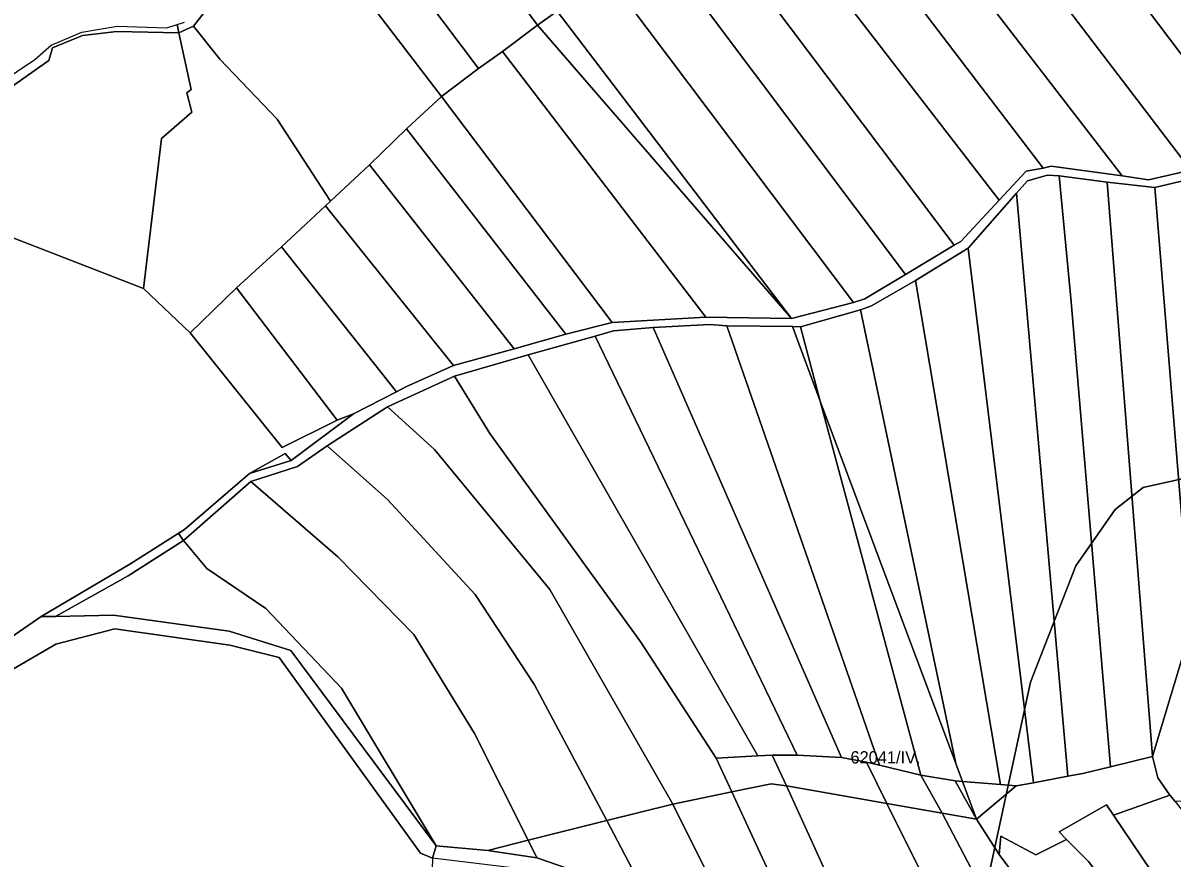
# Model space of a CAD drawing. Extents: x -521261 to -517465, y -1182764 to -1179456.
# Drawn here: x -520232.1 to -519763.3, y -1180556.2 to -1180215.6 of the extents above; entities that cross this region are included whole.
import ezdxf

# ---------------------------------------------------------------- set-up
doc = ezdxf.new("R2010")
doc.units = 0
for name, color, linetype in [('95560013', 7, 'Continuous'), ('95610013', 7, 'Continuous'), ('95620013', 7, 'Continuous'), ('95630013', 7, 'Continuous'), ('95640013', 7, 'Continuous'), ('95660013', 7, 'Continuous')]:
    doc.layers.add(name, color=color, linetype=linetype)

msp = doc.modelspace()

# ---------------------------------------------------------------- linework, layer by layer
at = {"layer": '95560013'}
for points in [[(-520022.17, -1180216.48), (-519918.48, -1180336.15), (-519953.52, -1180335.52), (-520036.42, -1180227.21)], [(-520036.42, -1180227.21), (-519953.52, -1180335.52), (-519991.66, -1180337.82), (-520061.32, -1180245.63), (-520046.22, -1180234.23)], [(-520061.32, -1180245.63), (-519991.66, -1180337.82), (-520010.61, -1180342.51), (-520075.57, -1180258.83)], [(-520075.57, -1180258.83), (-520010.61, -1180342.51), (-520031.68, -1180348.45), (-520090.76, -1180273.4)], [(-520090.76, -1180273.4), (-520031.68, -1180348.45), (-520056.48, -1180355.33), (-520108.66, -1180290.13), (-520106.59, -1180288.3)], [(-520108.66, -1180290.13), (-520056.48, -1180355.33), (-520075.93, -1180364.03), (-520079.72, -1180366), (-520126.56, -1180306.85)], [(-520126.56, -1180306.85), (-520079.72, -1180366), (-520097.16, -1180375.07), (-520103.92, -1180377.53), (-520144.91, -1180323.68)], [(-520163.84, -1180341.94), (-520144.91, -1180323.68), (-520103.92, -1180377.53), (-520126.31, -1180388.7)], [(-519991.21, -1180341.16), (-519975, -1180339.84), (-519898.1, -1180515.17), (-519916.26, -1180514.28), (-519998.64, -1180343.32)], [(-519951.87, -1180338.63), (-519944.96, -1180339.1), (-519882.63, -1180518.25), (-519887.93, -1180517.13), (-519898.1, -1180515.17), (-519975, -1180339.84)], [(-519918.17, -1180339.42), (-519906.77, -1180369.91), (-519865.71, -1180522.36), (-519882.63, -1180518.25), (-519944.96, -1180339.1)], [(-519998.64, -1180343.32), (-519916.26, -1180514.28), (-519926.4, -1180514.22), (-519932.3, -1180514.44), (-520025.91, -1180350.97)], [(-520056.04, -1180359.66), (-520025.91, -1180350.97), (-519932.3, -1180514.44), (-519949.33, -1180515.46), (-519979.96, -1180468.18), (-520041.61, -1180383.08)], [(-520056.04, -1180359.66), (-520041.61, -1180383.08), (-519979.96, -1180468.18), (-519949.33, -1180515.46), (-519942.92, -1180529.19), (-519966.95, -1180534.21), (-520017.18, -1180446.68), (-520064.12, -1180389.52), (-520083.39, -1180372.18)], [(-519906.77, -1180369.91), (-519851.55, -1180517.62), (-519848.8, -1180524.97), (-519851.74, -1180524.68), (-519865.71, -1180522.36)], [(-520083.39, -1180372.18), (-520064.12, -1180389.52), (-520017.18, -1180446.68), (-519966.95, -1180534.21), (-519993.87, -1180540.91), (-520023.31, -1180485.47), (-520047.54, -1180448.63), (-520083.31, -1180409.99), (-520107.95, -1180388.03)], [(-520120.07, -1180396.51), (-520107.95, -1180388.03), (-520083.31, -1180409.99), (-520047.54, -1180448.63), (-520023.31, -1180485.47), (-519993.87, -1180540.91), (-520025.98, -1180548.95), (-520047.89, -1180505.42), (-520072.54, -1180464.95), (-520103.68, -1180433.34), (-520139.1, -1180402.64)], [(-520139.1, -1180402.64), (-520103.68, -1180433.34), (-520072.54, -1180464.95), (-520047.89, -1180505.42), (-520025.98, -1180548.95), (-520042.35, -1180553.05), (-520063.47, -1180551.19), (-520102.14, -1180486.95), (-520132.98, -1180454.38), (-520157.02, -1180438.05), (-520166.58, -1180426.67)], [(-519926.4, -1180514.22), (-519920.55, -1180526.74), (-519926.76, -1180525.85), (-519942.92, -1180529.19), (-519949.33, -1180515.46), (-519932.3, -1180514.44)], [(-519916.26, -1180514.28), (-519898.1, -1180515.17), (-519887.93, -1180517.13), (-519879.66, -1180533.88), (-519920.55, -1180526.74), (-519926.4, -1180514.22)], [(-519882.63, -1180518.25), (-519865.71, -1180522.36), (-519857.1, -1180537.86), (-519879.66, -1180533.88), (-519887.93, -1180517.13)], [(-519926.76, -1180525.85), (-519920.55, -1180526.74), (-519881.21, -1180613), (-519902.42, -1180605.56), (-519908.84, -1180602.74), (-519942.92, -1180529.19)], [(-519865.71, -1180522.36), (-519851.74, -1180524.68), (-519843.08, -1180540.27), (-519857.1, -1180537.86)], [(-519851.74, -1180524.68), (-519848.8, -1180524.97), (-519843.08, -1180540.27)], [(-519942.92, -1180529.19), (-519908.84, -1180602.74), (-519920.76, -1180597.55), (-519921.12, -1180601.42), (-519937.24, -1180593.79), (-519966.95, -1180534.21)], [(-519879.66, -1180533.88), (-519853.6, -1180586.17), (-519837.56, -1180621.72), (-519856.32, -1180622.11), (-519868.13, -1180619.64), (-519872.32, -1180616.13), (-519881.21, -1180613), (-519920.55, -1180526.74)], [(-519966.95, -1180534.21), (-519937.24, -1180593.79), (-519977.79, -1180571.45), (-519993.87, -1180540.91)], [(-519857.1, -1180537.86), (-519836.41, -1180577.26), (-519816.49, -1180618.3), (-519837.56, -1180621.72), (-519853.6, -1180586.17), (-519879.66, -1180533.88)], [(-519843.08, -1180540.27), (-519833.76, -1180554.68), (-519824.12, -1180567.61), (-519814.57, -1180584.59), (-519801.81, -1180615.54), (-519816.49, -1180618.3), (-519836.41, -1180577.26), (-519857.1, -1180537.86)], [(-519993.87, -1180540.91), (-519977.79, -1180571.45), (-520022.38, -1180556.11), (-520025.98, -1180548.95)], [(-520025.98, -1180548.95), (-520022.38, -1180556.11), (-520042.35, -1180553.05)]]:
    msp.add_lwpolyline(points, close=True, dxfattribs=at)
at = {"layer": '95610013'}
for points in [[(-520087.72, -1180084.77), (-520000.02, -1180200.22), (-520014.19, -1180210.81), (-520022.17, -1180216.48), (-520103.91, -1180106.03), (-520102.56, -1180098.8)], [(-520116.98, -1180120.03), (-520103.91, -1180106.03), (-520022.17, -1180216.48), (-520036.42, -1180227.21), (-520046.22, -1180234.23), (-520111.5, -1180147.38), (-520109.04, -1180140.91), (-520114.85, -1180130.78)], [(-519918.98, -1180139.67), (-519910.54, -1180133.73), (-519890.27, -1180139.7), (-519783.6, -1180277.97), (-519812.59, -1180274.07), (-519815.81, -1180274.77)], [(-519835.13, -1180150.59), (-519831.45, -1180133.03), (-519728.44, -1180269.51), (-519755.62, -1180275.58), (-519853.23, -1180147.55)], [(-519831.45, -1180133.03), (-519803.64, -1180138.53), (-519789.06, -1180152.46), (-519727.7, -1180228.32), (-519707.67, -1180253.78), (-519700.26, -1180265.82), (-519721.33, -1180267.92), (-519728.44, -1180269.51)], [(-519919.82, -1180140.2), (-519918.98, -1180139.67), (-519815.81, -1180274.77), (-519822.85, -1180276.07), (-519833.8, -1180287.85), (-519937.67, -1180153.26)], [(-519890.27, -1180139.7), (-519877.12, -1180143.5), (-519853.23, -1180147.55), (-519755.62, -1180275.58), (-519772.88, -1180279.56), (-519783.6, -1180277.97)], [(-520116.25, -1180160.07), (-520111.5, -1180147.38), (-520046.22, -1180234.23), (-520061.32, -1180245.63), (-520121.89, -1180166.52)], [(-519956.53, -1180167.71), (-519937.67, -1180153.26), (-519833.8, -1180287.85), (-519849.46, -1180304.7), (-519852.14, -1180306.23)], [(-520134.31, -1180180.81), (-520121.89, -1180166.52), (-520061.32, -1180245.63), (-520075.57, -1180258.83), (-520090.76, -1180273.4), (-520106.59, -1180288.3), (-520128.4, -1180254.85), (-520151.79, -1180230.3), (-520162.47, -1180216.91)], [(-519974.75, -1180181.45), (-519956.53, -1180167.71), (-519852.14, -1180306.23), (-519872.04, -1180318.25)], [(-519977.7, -1180183.67), (-519974.75, -1180181.45), (-519872.04, -1180318.25), (-519888.59, -1180328.13), (-519893.18, -1180329.64), (-519994.04, -1180195.73)], [(-520000.02, -1180200.22), (-519994.04, -1180195.73), (-519893.18, -1180329.64), (-519918.48, -1180336.15), (-520014.19, -1180210.81)], [(-520022.17, -1180216.48), (-520014.19, -1180210.81), (-519918.48, -1180336.15)], [(-520168.49, -1180219.56), (-520162.47, -1180216.91), (-520151.79, -1180230.3), (-520128.4, -1180254.85), (-520106.59, -1180288.3), (-520108.66, -1180290.13), (-520126.56, -1180306.85), (-520144.91, -1180323.68), (-520163.84, -1180341.94), (-520182.93, -1180323.91), (-520175.62, -1180262.73), (-520163.16, -1180251.92), (-520165.16, -1180244.05), (-520163.46, -1180242.69)], [(-519770.35, -1180282.7), (-519744.97, -1180276.76), (-519737.48, -1180458.88), (-519747.26, -1180461.14), (-519755.56, -1180462.83)], [(-519814.05, -1180277.66), (-519809.35, -1180278), (-519804.49, -1180329.28), (-519788.39, -1180518.96), (-519799.62, -1180521.69), (-519805.84, -1180522.73), (-519826.73, -1180285.02), (-519822.24, -1180279.93)], [(-519789.79, -1180280.5), (-519771.26, -1180514.7), (-519788.39, -1180518.96), (-519804.49, -1180329.28), (-519809.35, -1180278)], [(-519770.35, -1180282.7), (-519755.56, -1180462.83), (-519771.26, -1180514.7), (-519789.79, -1180280.5)], [(-519846.4, -1180307.38), (-519826.73, -1180285.02), (-519805.84, -1180522.73), (-519819.83, -1180525.45)], [(-519846.4, -1180307.38), (-519819.83, -1180525.45), (-519826.92, -1180526.68), (-519833.27, -1180526.19), (-519867.92, -1180320.59)], [(-519885.85, -1180330.93), (-519867.92, -1180320.59), (-519833.27, -1180526.19), (-519848.8, -1180524.97), (-519851.55, -1180517.62), (-519890.34, -1180332.55)], [(-519890.34, -1180332.55), (-519851.55, -1180517.62), (-519906.77, -1180369.91), (-519914.92, -1180339.47)], [(-519914.92, -1180339.47), (-519906.77, -1180369.91), (-519918.17, -1180339.42)], [(-519755.56, -1180462.83), (-519747.26, -1180461.14), (-519742.58, -1180525.52), (-519741.98, -1180532.57), (-519762, -1180533.09), (-519764.17, -1180530.48), (-519769.07, -1180523.42), (-519771.26, -1180514.7)], [(-519771.26, -1180514.7), (-519769.07, -1180523.42), (-519764.17, -1180530.48), (-519787.11, -1180538.74), (-519790.04, -1180534.46), (-519809.29, -1180545.42), (-519806.32, -1180548.59), (-519818.8, -1180554.91), (-519833.18, -1180547.3), (-519833.76, -1180554.68), (-519843.08, -1180540.27), (-519826.92, -1180526.68), (-519819.83, -1180525.45), (-519805.84, -1180522.73), (-519799.62, -1180521.69), (-519788.39, -1180518.96)], [(-519848.8, -1180524.97), (-519833.27, -1180526.19), (-519826.92, -1180526.68), (-519843.08, -1180540.27)], [(-519762, -1180533.09), (-519756.87, -1180539.77), (-519746.34, -1180566.13), (-519737.99, -1180583.64), (-519734.67, -1180590.12), (-519723.97, -1180611.09), (-519747.7, -1180614.18), (-519755.66, -1180592.71), (-519768.22, -1180566.74), (-519787.11, -1180538.74), (-519764.17, -1180530.48)], [(-519787.11, -1180538.74), (-519768.22, -1180566.74), (-519755.66, -1180592.71), (-519747.7, -1180614.18), (-519764.44, -1180616.17), (-519787.86, -1180570.19), (-519797.31, -1180557.63), (-519806.32, -1180548.59), (-519809.29, -1180545.42), (-519790.04, -1180534.46)], [(-519833.18, -1180547.3), (-519818.8, -1180554.91), (-519806.32, -1180548.59), (-519797.31, -1180557.63), (-519787.86, -1180570.19), (-519764.44, -1180616.17), (-519801.81, -1180615.54), (-519814.57, -1180584.59), (-519824.12, -1180567.61), (-519833.76, -1180554.68)]]:
    msp.add_lwpolyline(points, close=True, dxfattribs=at)
at = {"layer": '95620013'}
for points in [[(-520168.49, -1180219.56), (-520163.46, -1180242.69), (-520165.16, -1180244.05), (-520163.16, -1180251.92), (-520175.62, -1180262.73), (-520182.93, -1180323.91), (-520247.51, -1180298.9), (-520279.33, -1180278.11), (-520276.87, -1180276.89), (-520267.87, -1180269.14), (-520254.23, -1180254.59), (-520250.78, -1180246.3), (-520248.23, -1180242.09), (-520243.06, -1180241.12), (-520239.04, -1180243.26), (-520221.51, -1180230.96), (-520220.08, -1180225.72), (-520207.81, -1180220.75), (-520193.76, -1180219.08)], [(-520125.16, -1180391.2), (-520122.61, -1180394.04), (-520139.65, -1180399.3)], [(-520166.58, -1180426.67), (-520157.02, -1180438.05), (-520132.98, -1180454.38), (-520102.14, -1180486.95), (-520063.47, -1180551.19), (-520122.8, -1180471.55), (-520147.94, -1180463.58), (-520195.07, -1180457.1), (-520218.82, -1180457.68), (-520189.1, -1180441.12)]]:
    msp.add_lwpolyline(points, close=True, dxfattribs=at)
for points in [[(-520247.51, -1180298.9), (-520182.93, -1180323.91), (-520163.84, -1180341.94), (-520126.31, -1180388.7), (-520103.92, -1180377.53), (-520097.16, -1180375.07), (-520122.61, -1180394.04), (-520125.16, -1180391.2), (-520139.65, -1180399.3), (-520166.22, -1180422.25), (-520188.46, -1180436.35), (-520224.7, -1180457.68), (-520267.22, -1180487.01)], [(-520561.44, -1180628.41), (-520418.21, -1180576.2), (-520359.3, -1180545.16), (-520250.11, -1180487.13), (-520218.6, -1180468.97), (-520194.59, -1180462.72), (-520147.74, -1180469.38), (-520127.48, -1180474.4), (-520069.86, -1180554.25), (-520065.03, -1180556.21), (-520065.13, -1180560.74), (-520065.1, -1180602.48), (-520061.92, -1180634.28), (-520056.64, -1180662.89), (-520055.03, -1180670.89), (-520054.03, -1180691.48), (-520052.16, -1180715.87), (-520084.17, -1180732.28), (-520085.42, -1180763.05), (-520080.76, -1180777.95), (-520260.96, -1180807.27), (-520437.72, -1180836.09), (-520517.73, -1180858.28)]]:
    msp.add_lwpolyline(points, dxfattribs=at)
at = {"layer": '95630013'}
for points in [[(-520134.31, -1180180.81), (-520162.47, -1180216.91), (-520168.49, -1180219.56), (-520193.76, -1180219.08), (-520207.81, -1180220.75), (-520220.08, -1180225.72), (-520221.51, -1180230.96), (-520239.04, -1180243.26)], [(-520241.51, -1180240.05), (-520227.21, -1180230.49), (-520220.55, -1180224.59), (-520208.09, -1180219.42), (-520193.68, -1180216.96), (-520173.43, -1180217.54), (-520166.13, -1180215.24)]]:
    msp.add_lwpolyline(points, dxfattribs=at)
at = {"layer": '95640013'}
for points in [[(-519744.97, -1180276.76), (-519770.35, -1180282.7), (-519789.79, -1180280.5), (-519809.35, -1180278), (-519814.05, -1180277.66), (-519822.24, -1180279.93), (-519826.73, -1180285.02), (-519846.4, -1180307.38), (-519867.92, -1180320.59), (-519885.85, -1180330.93), (-519890.34, -1180332.55), (-519914.92, -1180339.47), (-519918.17, -1180339.42), (-519944.96, -1180339.1), (-519951.87, -1180338.63), (-519975, -1180339.84), (-519991.21, -1180341.16), (-519998.64, -1180343.32), (-520025.91, -1180350.97), (-520056.04, -1180359.66), (-520083.39, -1180372.18), (-520107.95, -1180388.03), (-520120.07, -1180396.51), (-520139.1, -1180402.64), (-520166.58, -1180426.67), (-520189.1, -1180441.12), (-520218.82, -1180457.68), (-520224.7, -1180457.68), (-520188.46, -1180436.35), (-520166.22, -1180422.25), (-520139.65, -1180399.3), (-520122.61, -1180394.04), (-520097.16, -1180375.07), (-520079.72, -1180366), (-520075.93, -1180364.03), (-520056.48, -1180355.33), (-520031.68, -1180348.45), (-520010.61, -1180342.51), (-519991.66, -1180337.82), (-519953.52, -1180335.52), (-519918.48, -1180336.15), (-519893.18, -1180329.64), (-519888.59, -1180328.13), (-519872.04, -1180318.25), (-519852.14, -1180306.23), (-519849.46, -1180304.7), (-519833.8, -1180287.85), (-519822.85, -1180276.07), (-519815.81, -1180274.77), (-519812.59, -1180274.07), (-519783.6, -1180277.97), (-519772.88, -1180279.56), (-519755.62, -1180275.58)], [(-520579.89, -1180626.79), (-520418.64, -1180567.25), (-520267.22, -1180487.01), (-520224.7, -1180457.68), (-520218.82, -1180457.68), (-520195.07, -1180457.1), (-520147.94, -1180463.58), (-520122.8, -1180471.55), (-520063.47, -1180551.19), (-520042.35, -1180553.05), (-520022.38, -1180556.11), (-519977.79, -1180571.45), (-519937.24, -1180593.79), (-519921.12, -1180601.42), (-519906.63, -1180607.48), (-519879.5, -1180616.96), (-519874.81, -1180618.65), (-519850.9, -1180639.04), (-519814.85, -1180668.94), (-519803.71, -1180675.31), (-519783.25, -1180694.48), (-519756.77, -1180721.21)], [(-519759.06, -1180725.67), (-519806.67, -1180679.04), (-519823.08, -1180668.31), (-519877.33, -1180621.85), (-519907.42, -1180611.79), (-519914.26, -1180609.63), (-519967.45, -1180581.52), (-519978.62, -1180575.67), (-520019.07, -1180561.78), (-520065.03, -1180556.21), (-520069.86, -1180554.25), (-520127.48, -1180474.4), (-520147.74, -1180469.38), (-520194.59, -1180462.72), (-520218.6, -1180468.97), (-520250.11, -1180487.13), (-520359.3, -1180545.16), (-520418.21, -1180576.2), (-520561.44, -1180628.41)]]:
    msp.add_lwpolyline(points, dxfattribs=at)
at = {"layer": '95660013'}
for points in [[(-520241.51, -1180240.05), (-520227.21, -1180230.49), (-520220.55, -1180224.59), (-520208.09, -1180219.42), (-520193.68, -1180216.96), (-520173.43, -1180217.54), (-520169.22, -1180216.21), (-520168.49, -1180219.56), (-520163.46, -1180242.69), (-520165.16, -1180244.05), (-520163.16, -1180251.92), (-520175.62, -1180262.73), (-520182.93, -1180323.91), (-520163.84, -1180341.94), (-520126.31, -1180388.7), (-520103.92, -1180377.53), (-520097.16, -1180375.07), (-520122.61, -1180394.04), (-520139.65, -1180399.3), (-520166.22, -1180422.25), (-520168.63, -1180423.78), (-520166.58, -1180426.67), (-520157.02, -1180438.05), (-520132.98, -1180454.38), (-520102.14, -1180486.95), (-520063.47, -1180551.19), (-520065.03, -1180556.21)], [(-520065.03, -1180556.21), (-520063.47, -1180551.19), (-520102.14, -1180486.95), (-520132.98, -1180454.38), (-520157.02, -1180438.05), (-520166.58, -1180426.67), (-520168.63, -1180423.78), (-520166.22, -1180422.25), (-520139.65, -1180399.3), (-520122.61, -1180394.04), (-520097.16, -1180375.07), (-520103.92, -1180377.53), (-520126.31, -1180388.7), (-520163.84, -1180341.94), (-520182.93, -1180323.91), (-520175.62, -1180262.73), (-520163.16, -1180251.92), (-520165.16, -1180244.05), (-520163.46, -1180242.69), (-520168.49, -1180219.56), (-520169.22, -1180216.21), (-520169.22, -1180216.21), (-520166.13, -1180215.24)], [(-519739, -1180397), (-519775, -1180405), (-519786.5, -1180414), (-519802.5, -1180437), (-519821, -1180484.5), (-519840.5, -1180574.5), (-519844.5, -1180642), (-519826.5, -1180739.5), (-519812, -1180786), (-519790.5, -1180844), (-519778.5, -1180863.5), (-519754.5, -1180885.5)], [(-519754.5, -1180885.5), (-519778.5, -1180863.5), (-519790.5, -1180844), (-519812, -1180786), (-519826.5, -1180739.5), (-519844.5, -1180642), (-519840.5, -1180574.5), (-519821, -1180484.5), (-519802.5, -1180437), (-519786.5, -1180414), (-519775, -1180405), (-519739, -1180397)]]:
    msp.add_lwpolyline(points, dxfattribs=at)

# ---------------------------------------------------------------- texts
msp.add_text('62041/IV.', height=5, dxfattribs=at).set_placement((-519894.47, -1180517.59))

doc.saveas('drawing.dxf')
